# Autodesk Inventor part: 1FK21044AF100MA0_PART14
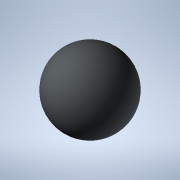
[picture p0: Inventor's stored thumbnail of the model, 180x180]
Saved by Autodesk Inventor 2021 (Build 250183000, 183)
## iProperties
Created: 2025-04
Part Number: 1FK21044AF100MA0_PART14
Material: Generic
Catalog Web Link: www.3dfindit.com
Description: -Servo synchronous motor
Document SubType Name: Modeling
Designer: psAdmin
Mass: 0.137258 g
Surface Area: 1.2868 cm^2
Volume: 0.137258 cm^3
Density: 1 g/cm^3
Appearance: PSOLRGB-212-217-219
Category: PARTsolutions
Title: 1FK21044AF100MA0_PART14
Author: Cadenas PARTsolutions
Comments: Servo synchronous motor
Sending System: PARTsolutions
Preprocessor: ST-DEVELOPER v19.3
PSOL_IDENT_0: {$CADENAS_DATA/23d-libs/siemens_ag/_cat_/ec/e4/1fk21044af100ma0.prj},216 {VTYP=3D},{NB=1FK21044AF100
PSOL_IDENT_1: MA0_PART14},{LINA=1FK21044AF100MA0_PART14},{NN=1FK21044AF100MA0_PART14},{NOPRJ=TRUE},{DATE=19.08.202
PSOL_IDENT_2: 5 14:01:05},{GEOMDATE=30.07.2025 02:01:01},{VERSION=},{LINEID=10},{WBVAR=},{WBNUMERIC=}  {NB=1FK2104
PSOL_IDENT_3: 4AF100MA0_PART14},{LINA=1FK21044AF100MA0_PART14},{KT=DUMMY},{PREVIEW=../../../_pool_/cb/72/p_d211_xx
PSOL_IDENT_4: _00434j.png},{DESCSHORT=SIMOTICS S-1FK2 HD, SINAMICS S210 3AC 400V-480V, 1.27 Nm, 3000 rpm},{DESCLON
PSOL_IDENT_5: G=SIMOTICS S-1FK2 HD servo motor M0=1.27 Nm; PN = 0.4 kW at nN=3000 rpm (380-480 V); PN = 0.2 kW at
PSOL_IDENT_6: nN=1500 rpm (200-240 V); with holding brake; degree of protection IP64; cylindrical shaft D19x40mm;
PSOL_IDENT_7: absolute encoder 22-bit + 12-bit multiturn (encoder AM22DQC); with OCC interface; plug size M17, rot
PSOL_IDENT_8: atable; SIMOTICS S-1FK2 servomotorfor a wide range of uses in industrial environments. SIMOTICS S‑1F
PSOL_IDENT_9: K2 servomotors are compact synchronous motors with a high dynamic performance that set themselves ap
PSOL_IDENT_10: art as a result of their high power density, degree of protection and overload capability. The motor
PSOL_IDENT_11: s are available in two variants: as High Dynamic variant (highest dynamic performance as a result of
PSOL_IDENT_12: the low intrinsic moment of inertia for applications demanding a high dynamic performance with low
PSOL_IDENT_13: moved masses) - and as Compact variant (precise and stable closed-loop control for medium up to larg
PSOL_IDENT_14: e moved masses as a result of a medium intrinsic moment of inertia). SIMOTICSS‑1FK2 servomotors full
PSOL_IDENT_15: y exploit their strengths in a system with the SINAMICSS210 frequency converter and simple connectio
PSOL_IDENT_16: n using the one cable connection (OCC). Advantages include the short control and positioning times,
PSOL_IDENT_17: fast and precise correction of disturbing quantities as well as stable control with a high dynamic p
PSOL_IDENT_18: erformance. The servo motors can be configured to address a wide range of requirements. For example
PSOL_IDENT_19: with and without holding brake, IP64 or IP65 degree of protection, singleturn or multiturn absolute
PSOL_IDENT_20: encoders - to name just a few. Further, the servomotors are available in different shaft heights ext
PSOL_IDENT_21: ending from 20 to 100. A shaft sealing ring is available to achieve an IP65 degree of protection and
PSOL_IDENT_22: for subsequent mounting at the motor or as spare part. SIMOTICS - the optimum motor for each and ev
PSOL_IDENT_23: ery motion control application.},{INTNO=195125043275},{SUPPLIERALTNO=1FK2104-4AF10-0MA0},{MANUID=1FK
PSOL_IDENT_24: 21044AF100MA0},{MANUNAME=Siemens},{MANUTYPEDESC=Synchronous motor 1FK2-HD 1.27 NM},{AAU732=SIMOTICS}
PSOL_IDENT_25: ,{AAO057=S-1FK2},{AAU734=SIMOTICS S-1FK2 HD servo motor M0=1.27 Nm; PN = 0.4 kW at nN=3000 rpm (380-
PSOL_IDENT_26: 480 V); PN = 0.2 kW at nN=1500 rpm (200-240 V); with holding brake; degree of protection IP64; cylin
PSOL_IDENT_27: drical shaft D19x40mm; absolute encoder 22-bit + 12-bit multiturn (encoder AM22DQC); with OCC interf
PSOL_IDENT_28: ace; plug size M17, rotatable;},{AAW338=Synchronous motor 1FK2-HD 1.27 NM},{AAO742=SIMOTICS},{AAO663=
PSOL_IDENT_29: 4042948694015},{NOCUPEROU=1},{PRICEQUANTITY=1},{QUANTITYMIN=1},{QUANTITYINT=1},{CTN=85015100},{COO=D
PSOL_IDENT_30: E},{AAO676=1FK2104-4AF10-0MA0},{AAO677=Siemens AG},{ORDERUNIT=C62},{CONTENTUNIT=C62}
NB: 1FK21044AF100MA0_PART14
NT: Servo synchronous motor
NBSYN: $MANUID._PART14
LINA: 1FK21044AF100MA0_PART14
CATALOG: SIEMENS
PREVIEW: ../../../_pool_/cb/72/p_d211_xx_00434j.png
DESCSHORT: SIMOTICS S-1FK2 HD, SINAMICS S210 3AC 400V-480V, 1.27 Nm, 3000 rpm
DESCLONG: SIMOTICS S-1FK2 HD servo motor M0=1.27 Nm; PN = 0.4 kW at nN=3000 rpm (380-480 V); PN = 0.2 kW at nN=1500 rpm (200-240 V); with holding brake; degree of protect
INTNO: 195125043275
SUPPLIERALTNO: 1FK2104-4AF10-0MA0
MANUID: 1FK21044AF100MA0
MANUNAME: Siemens
MANUTYPEDESC: Synchronous motor 1FK2-HD 1.27 NM
AAU732: SIMOTICS
AAO057: S-1FK2
AAU734: SIMOTICS S-1FK2 HD servo motor M0=1.27 Nm; PN = 0.4 kW at nN=3000 rpm (380-480 V); PN = 0.2 kW at nN=1500 rpm (200-240 V); with holding brake; degree of protect
AAW338: Synchronous motor 1FK2-HD 1.27 NM
AAO742: SIMOTICS
AAO663: 4042948694015.0
NOCUPEROU: 1
PRICEQUANTITY: 1
QUANTITYMIN: 1
QUANTITYINT: 1
CTN: 85015100
COO: DE
ARTICLENO: 1FK21044AF100MA0_PART14
BOMINFO: 1FK21044AF100MA0_PART14
CREATOR: CADENAS GmbH
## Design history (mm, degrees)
feature "2025_04_17_15_33_01_0673"
body "Solid1"
